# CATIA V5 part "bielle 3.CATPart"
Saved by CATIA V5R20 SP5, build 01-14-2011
Part number: bielle 3
Bounding box of the stored display mesh (mm): x 2728.052 to 11748.765, y -250 to 250, z 5579.339 to 13280.076
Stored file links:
  M:\EU_thinkMotion\IAO_2010\iao\IAO_MMS_Groupe1\Problemes\gduval\Gduval\train d'aterrissage squelette + piece kinematic\bielle 3.CATPart
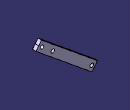
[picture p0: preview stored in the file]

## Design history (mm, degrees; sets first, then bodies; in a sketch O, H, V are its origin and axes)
Body1 (main body)
  Point1: stored without definition
  Point2: stored without definition
  Sketch1 on zx-plane, origin (0, 0, 0), H (-1, 0, 0), V (0, 0, 1)
    axis line L1 (-11300.1735, 12745.9547) -> (-2947.2063, 5926.1361)
    reference projected point E1 (-3562.187, 6428.24) from Point1
    reference projected point E2 (-10834.35, 12365.631) from Point2
    line L2 (-3139.1351, 6082.8373) -> (-2728.0517, 6586.3355)
    point P3 (-3139.1351, 6082.8373)
    point P4 (-2728.0517, 6586.3355)
    reference projected point E3 (-3562.187, 6428.24) from Point1
    line L3 (-2728.0517, 6586.3355) -> (-10926.5982, 13280.0766)
    point P5 (-10926.5982, 13280.0766)
    line L4 (-10926.5982, 13280.0766) -> (-11337.6816, 12776.5784)
    point P6 (-10926.5982, 13280.0766)
    point P7 (-11337.6816, 12776.5784)
    reference projected point E4 (-10834.35, 12365.631) from Point2
    point P8 (-11748.765, 12273.0802)
    point P9 (-3550.2185, 5579.3391)
    line L5 (-3550.2185, 5579.3391) -> (-11748.765, 12273.0802)
    point P10 (-11337.6816, 12776.5784)
    point P11 (-11748.765, 12273.0802)
    line L6 (-11748.765, 12273.0802) -> (-11337.6816, 12776.5784)
    point P12 (-3139.1351, 6082.8373)
    line L7 (-3139.1351, 6082.8373) -> (-3550.2185, 5579.3391)
    distance E3 L2 = 546.1465
    distance L4 E4 = 649.7849
    distance L3 L1 = 650
    coincidence: L1 E1, L1 E2, P3 L1, P6 L3, P7 L1, P6 P5, P3 P12, P7 P10, P8 P11
    perpendicularity: L2 L1, L4 L1
    symmetry: P5 P8 L1, P4 P9 L1, L3 L5 L1, P7 P10 L1, P6 P11 L1, L4 L6 L1, P3 P12 L1, L2 L7 L1
  Pad1: profile Sketch1, direction (0, 1, 0), length 250, mirrored extent
  Sketch2 on start face of Pad1, origin (3562.187, -250, 6428.24), H (1, 0, 0), V (0, 0, 1)
    point P1 (0, 0)
    reference projected point E1 (0, 0) from Point1
    coincidence: E1 P1
  Hole1: placed by Sketch2, at (3562.187, -250, 6428.24) direction (0, 1, 0), diameter 520, through (limit type 6)
  Point3: stored without definition
  Sketch3 on start face of Pad1, origin (10834.35, -250, 12365.631), H (1, 0, 0), V (0, 0, 1)
    point P1 (0, 0)
    reference projected point E1 (0, 0) from Point2
    coincidence: E1 P1
  Hole2: placed by Sketch3, at (10834.35, -250, 12365.631) direction (0, 1, 0), diameter 520, through (limit type 6)
  Sketch4 on start face of Pad1, origin (9261.784, -250, 11081.702), H (1, 0, 0), V (0, 0, 1)
    point P1 (0, 0)
    reference projected point E1 (0, 0) from Point3
    coincidence: E1 P1
  Hole3: placed by Sketch4, at (9261.784, -250, 11081.702) direction (0, 1, 0), diameter 520, through (limit type 6)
